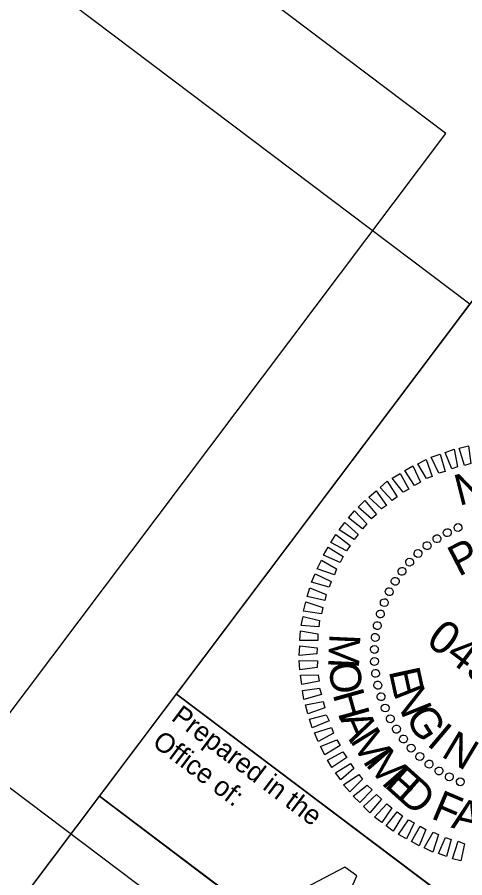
# Model space of a CAD drawing. Extents: x 2296955 to 2298159, y 600182 to 601317.
# Drawn here: x 2297972.1 to 2298027.2, y 600681.2 to 600787.1 of the extents above; entities that cross this region are included whole.
import ezdxf

# ---------------------------------------------------------------- set-up
doc = ezdxf.new("R2010")
doc.units = 0
for name, color, linetype in [('Default', 7, 'Continuous'), ('Exist DTM Drainline Cogo Elevation', 7, 'Continuous'), ('Exist Property Iron Pin Cogo Number', 7, 'Continuous'), ('Exist Roads Curbs Cogo Comment', 7, 'Continuous'), ('Exist Roads Curbs Cogo Elevation', 7, 'Continuous'), ('Exist Roads Curbs Cogo Number', 7, 'Continuous'), ('Exist Roads EOP Cogo Comment', 7, 'Continuous'), ('Exist Roads EOP Cogo Elevation', 7, 'Continuous'), ('Exist Roads EOP Other Cogo Point CELL', 7, 'Continuous')]:
    doc.layers.add(name, color=color, linetype=linetype)

# ---------------------------------------------------------------- blocks, each defined once
blk = doc.blocks.new('POINT_DISPLAY')
at = {"layer": 'Default'}
blk.add_line((0, 0), (0, 0), dxfattribs=at)

msp = doc.modelspace()

# ---------------------------------------------------------------- linework, layer by layer
at = {"layer": 'Exist DTM Drainline Cogo Elevation'}
msp.add_lwpolyline([(2298032.37, 600757.74), (2298080.31, 600721.61), (2298039.68, 600667.71), (2297991.74, 600703.83)], close=True, dxfattribs=at)
at = {"layer": 'Exist Property Iron Pin Cogo Number'}
msp.add_lwpolyline([(2297342.87, 601088.91), (2297238.27, 600783.77), (2297197.22, 600664.01), (2297465.89, 600461.56), (2297631.65, 600336.65), (2298039.33, 600622.14), (2298039.33, 600622.14), (2297969.72, 600674.6), (2298027.87, 600751.78), (2297428.93, 601203.11)], close=True, dxfattribs=at)
at = {"layer": 'Exist Roads Curbs Cogo Comment'}
msp.add_lwpolyline([(2297991.74, 600703.83), (2298087.58, 600631.61), (2298078.1, 600619.04), (2297982.26, 600691.26)], close=True, dxfattribs=at)
at = {"layer": 'Exist Roads Curbs Cogo Elevation'}
for p, q in [((2297973.78, 600679.99), (2297982.26, 600691.26)), ((2297982.26, 600691.26), (2298078.12, 600619.02))]:
    msp.add_line(p, q, dxfattribs=at)
at = {"layer": 'Exist Roads Curbs Cogo Number'}
msp.add_lwpolyline([(2297423.02, 601245.14), (2297043.89, 600742.01), (2297762.65, 600200.36), (2298069.63, 600607.76), (2297973.78, 600679.99), (2298045.93, 600775.73)], close=True, dxfattribs=at)
at = {"layer": 'Exist Roads EOP Cogo Comment'}
msp.add_lwpolyline([(2297425.97, 601224.13), (2297064.9, 600744.96), (2297759.7, 600221.37), (2298062.62, 600623.38), (2297966.76, 600695.61), (2298024.92, 600772.78)], close=True, dxfattribs=at)
at = {"layer": 'Exist Roads EOP Cogo Elevation'}
for p, q in [((2298012.49, 600682.55), (2298005.89, 600679.07)), ((2298013.95, 600681.45), (2298012.49, 600682.55)), ((2298011.14, 600675.12), (2298013.95, 600681.45))]:
    msp.add_line(p, q, dxfattribs=at)
msp.add_lwpolyline([(2298009.85, 600676.09), (2298011.14, 600675.12), (2298013.95, 600681.45), (2298012.49, 600682.55), (2298005.89, 600679.07), (2298007.25, 600678.05), (2298008.48, 600678.77), (2298010.42, 600677.31), (2298009.85, 600676.09)], dxfattribs=at)
at = {"layer": 'Exist Roads EOP Other Cogo Point CELL'}
for points in [[(2298027.21, 600731.96), (2298026.57, 600734.09), (2298027.69, 600734.34), (2298027.97, 600732.19)], [(2298024.04, 600731.01), (2298023.09, 600732.95), (2298024.19, 600733.34), (2298024.83, 600731.21)], [(2298025.65, 600731.52), (2298024.84, 600733.53), (2298025.94, 600733.93), (2298026.36, 600731.79)], [(2298022.52, 600730.34), (2298021.47, 600732.14), (2298022.48, 600732.69), (2298023.23, 600730.6)], [(2298021.07, 600729.48), (2298019.85, 600731.33), (2298020.85, 600731.89), (2298021.79, 600729.87)], [(2298019.64, 600728.65), (2298018.32, 600730.37), (2298019.27, 600730.96), (2298020.34, 600729.02)], [(2298018.29, 600727.65), (2298016.84, 600729.25), (2298017.7, 600730), (2298018.91, 600728.07)], [(2298016.99, 600726.59), (2298015.44, 600728.06), (2298016.32, 600728.84), (2298017.61, 600727.02)], [(2298015.74, 600725.38), (2298014.12, 600726.82), (2298014.92, 600727.65), (2298016.36, 600725.93)], [(2298014.66, 600724.17), (2298012.91, 600725.49), (2298013.65, 600726.36), (2298015.2, 600724.77)], [(2298013.64, 600722.82), (2298011.79, 600724.01), (2298012.48, 600724.92), (2298014.13, 600723.47)], [(2298012.68, 600721.43), (2298010.73, 600722.48), (2298011.36, 600723.44), (2298013.11, 600722.12)], [(2298011.89, 600720), (2298009.84, 600720.91), (2298010.42, 600721.91), (2298012.25, 600720.74)], [(2298011.19, 600718.5), (2298009.08, 600719.24), (2298009.59, 600720.3), (2298011.43, 600719.21)], [(2298010.54, 600716.96), (2298008.35, 600717.59), (2298008.83, 600718.63), (2298010.78, 600717.67)], [(2298010.02, 600715.32), (2298007.85, 600715.81), (2298008.16, 600716.89), (2298010.18, 600716.09)], [(2298009.6, 600713.7), (2298007.4, 600714.04), (2298007.66, 600715.16), (2298009.78, 600714.49)], [(2298009.29, 600712.11), (2298007.08, 600712.26), (2298007.33, 600713.38), (2298009.35, 600712.87)], [(2298009.15, 600710.4), (2298006.93, 600710.43), (2298007, 600711.59), (2298009.13, 600711.22)], [(2298009.01, 600708.77), (2298006.85, 600708.58), (2298006.92, 600709.75), (2298009.08, 600709.52)], [(2298009.08, 600707.11), (2298006.93, 600706.79), (2298006.87, 600707.94), (2298009.09, 600707.91)], [(2298009.32, 600705.41), (2298007.18, 600704.99), (2298007.02, 600706.13), (2298009.21, 600706.17)], [(2298009.6, 600703.77), (2298007.44, 600703.15), (2298007.28, 600704.28), (2298009.37, 600704.53)], [(2298010.02, 600702.14), (2298007.93, 600701.38), (2298007.63, 600702.5), (2298009.79, 600702.9)], [(2298010.53, 600700.52), (2298008.44, 600699.65), (2298008.14, 600700.72), (2298010.18, 600701.29)], [(2298011.08, 600699.01), (2298009.21, 600697.97), (2298008.72, 600699.06), (2298010.82, 600699.72)], [(2298011.88, 600697.48), (2298010.01, 600696.35), (2298009.46, 600697.36), (2298011.49, 600698.2)], [(2298012.73, 600696.03), (2298010.86, 600694.78), (2298010.32, 600695.69), (2298012.23, 600696.71)], [(2298013.6, 600694.66), (2298011.96, 600693.27), (2298011.31, 600694.15), (2298013.18, 600695.28)], [(2298014.65, 600693.36), (2298013.09, 600691.79), (2298012.31, 600692.67), (2298014.18, 600693.92)], [(2298015.82, 600692.06), (2298014.31, 600690.49), (2298013.5, 600691.27), (2298015.23, 600692.63)], [(2298016.97, 600690.89), (2298015.57, 600689.2), (2298014.78, 600690.01), (2298016.39, 600691.46)], [(2298018.28, 600689.82), (2298017.01, 600688.03), (2298016.12, 600688.7), (2298017.63, 600690.31)], [(2298019.57, 600688.85), (2298018.44, 600686.95), (2298017.55, 600687.62), (2298018.93, 600689.34)], [(2298021.02, 600687.97), (2298020.07, 600686.02), (2298019.08, 600686.56), (2298020.32, 600688.37)], [(2298022.46, 600687.18), (2298021.64, 600685.14), (2298020.67, 600685.7), (2298021.75, 600687.59)], [(2298024, 600686.53), (2298023.31, 600684.38), (2298022.25, 600684.89), (2298023.33, 600686.82)], [(2298025.58, 600685.93), (2298025, 600683.83), (2298023.99, 600684.21), (2298024.87, 600686.17)], [(2298027.22, 600685.42), (2298026.77, 600683.3), (2298025.74, 600683.57), (2298026.43, 600685.71)]]:
    msp.add_lwpolyline(points, close=True, dxfattribs=at)
for centre, major_axis in [((2298026.41, 600724.31), (-0.19, 0.447)), ((2298025.08, 600723.68), (-0.228, 0.429)), ((2298023.81, 600722.93), (-0.265, 0.408)), ((2298021.48, 600721.11), (-0.332, 0.356)), ((2298022.6, 600722.07), (-0.299, 0.383)), ((2298020.45, 600720.06), (-0.361, 0.325)), ((2298019.51, 600718.92), (-0.388, 0.293)), ((2298018.67, 600717.7), (-0.412, 0.258)), ((2298017.94, 600716.42), (-0.433, 0.221)), ((2298017.33, 600715.07), (-0.451, 0.182)), ((2298016.84, 600713.68), (-0.465, 0.142)), ((2298016.47, 600712.25), (-0.475, 0.101)), ((2298016.22, 600710.79), (-0.482, 0.059)), ((2298016.11, 600709.32), (-0.486, 0.017)), ((2298016.12, 600707.84), (-0.485, -0.025)), ((2298016.26, 600706.37), (-0.481, -0.068)), ((2298016.53, 600704.92), (-0.474, -0.109)), ((2298016.92, 600703.5), (-0.462, -0.15)), ((2298017.44, 600702.11), (-0.447, -0.19)), ((2298018.08, 600700.78), (-0.429, -0.228)), ((2298018.83, 600699.51), (-0.408, -0.265)), ((2298019.69, 600698.3), (-0.383, -0.299)), ((2298020.64, 600697.18), (-0.356, -0.332)), ((2298021.7, 600696.14), (-0.325, -0.361)), ((2298022.84, 600695.21), (-0.293, -0.388)), ((2298024.06, 600694.37), (-0.258, -0.412)), ((2298025.34, 600693.64), (-0.221, -0.433)), ((2298026.69, 600693.03), (-0.182, -0.451))]:
    msp.add_ellipse(centre, major_axis=major_axis, ratio=0.999708, dxfattribs=at)

# ---------------------------------------------------------------- block references
at = {"layer": 'Exist Roads EOP Other Cogo Point CELL', "xscale": 41.411959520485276, "yscale": 41.411959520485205, "rotation": -37.000428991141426}
for p in [(2298026.4, 600724.32), (2298023.8, 600722.95), (2298025.07, 600723.68), (2298022.59, 600722.08), (2298021.48, 600721.1), (2298020.44, 600720.06), (2298019.49, 600718.92), (2298018.65, 600717.69), (2298017.94, 600716.41), (2298017.31, 600715.07), (2298016.81, 600713.67), (2298016.1, 600709.31), (2298016.09, 600707.83), (2298016.25, 600706.36), (2298016.5, 600704.9), (2298016.91, 600703.49), (2298017.42, 600702.09), (2298018.07, 600700.76), (2298018.8, 600699.49), (2298019.67, 600698.29), (2298020.65, 600697.17), (2298021.68, 600696.14), (2298022.83, 600695.19), (2298024.06, 600694.35), (2298025.34, 600693.64), (2298026.68, 600693)]:
    msp.add_blockref('POINT_DISPLAY', p, dxfattribs=at)

# ---------------------------------------------------------------- texts
at = {"layer": 'Exist Roads EOP Cogo Elevation'}
for s, p in [('Prepared in the ', (2297990.98, 600700.7)), ('Office of:', (2297988.63, 600697.59))]:
    msp.add_text(s, height=2.4, rotation=322.9991, dxfattribs=at).set_placement(p)
at = {"layer": 'Exist Roads EOP Other Cogo Point CELL'}
for s, height, rotation, p in [('N', 3.81, 14.16, (2298026.53, 600726.97)), ('P', 3.81, 27.3985, (2298026.49, 600718.22)), ('049634', 4.051, 322.9996, (2298022.3, 600710.08)), ('M', 3.81, 267.4103, (2298010.59, 600711.3)), ('O', 3.81, 276.5063, (2298010.46, 600707.6)), ('E', 3.81, 282.2765, (2298017.87, 600706.67)), ('N', 3.81, 291.6335, (2298018.41, 600704.01)), ('H', 3.81, 285.6647, (2298010.95, 600703.82)), ('G', 3.81, 302.5028, (2298019.81, 600700.94)), ('A', 3.81, 293.5487, (2298011.83, 600700.81)), ('M', 3.81, 301.925, (2298013.03, 600698.13)), ('I', 3.81, 319.7008, (2298022.44, 600697.63)), ('N', 3.81, 329.056, (2298024.2, 600696.22)), ('M', 3.81, 311.016, (2298014.93, 600695.13)), ('E', 3.81, 318.1426, (2298017.23, 600692.5)), ('D', 3.81, 318.1426, (2298018.72, 600691.17)), ('F', 3.81, 337.0823, (2298022.95, 600688.59)), ('A', 3.81, 346.983, (2298025.47, 600687.41))]:
    msp.add_text(s, height=height, rotation=rotation, dxfattribs=at).set_placement(p)

doc.saveas('drawing.dxf')
